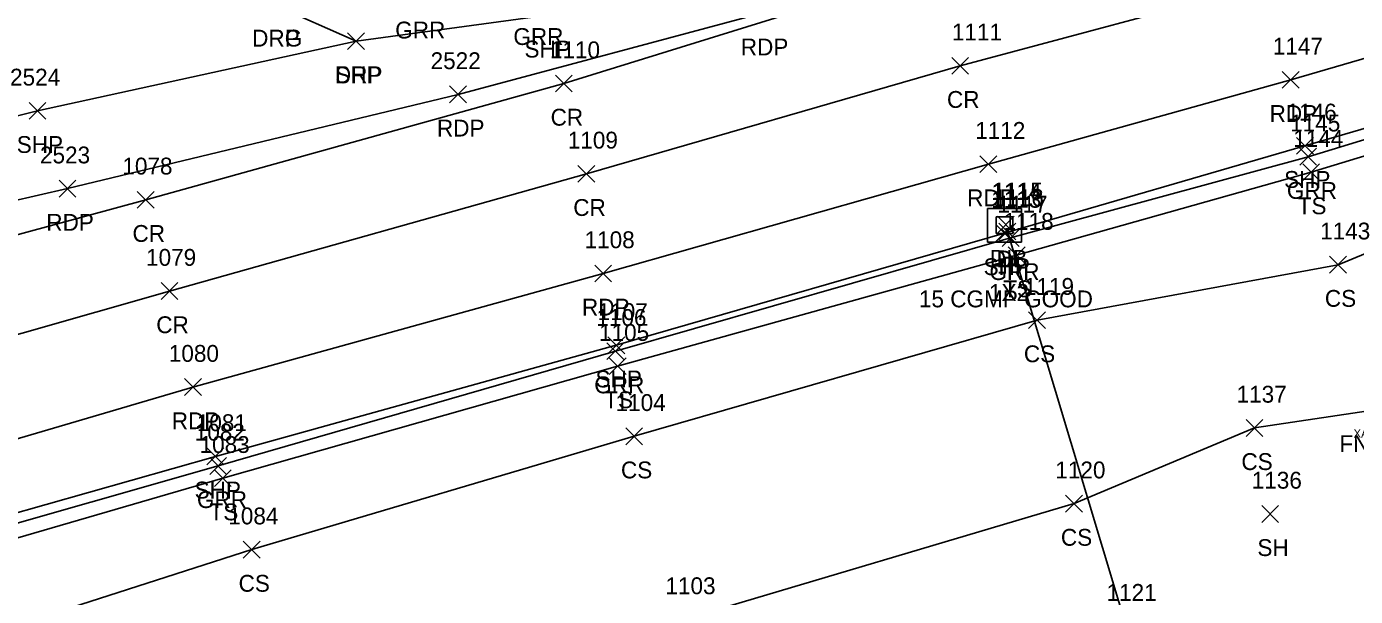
# Model space of a CAD drawing. Extents: x 49137 to 50946, y 9590 to 10709.
# Drawn here: x 49768.6 to 49926.3, y 9933.2 to 10000.8 of the extents above; entities that cross this region are included whole.
import ezdxf

# ---------------------------------------------------------------- set-up
doc = ezdxf.new("R2010")
doc.units = 0
for name, color, linetype in [('B_A', 7, 'Continuous'), ('D_A', 7, 'Continuous'), ('D_C', 7, 'Continuous'), ('D_I', 7, 'Continuous'), ('D_TIC', 7, 'Continuous'), ('DCP', 7, 'Continuous'), ('DS', 7, 'Continuous'), ('L_A', 7, 'Continuous'), ('L_I', 7, 'Continuous'), ('L_TIC', 7, 'Continuous'), ('LELB', 7, 'Continuous'), ('P_A', 7, 'Continuous'), ('P_I', 7, 'Continuous'), ('P_TIC', 7, 'Continuous'), ('PET', 7, 'Continuous'), ('PRC', 7, 'Continuous'), ('PSP', 7, 'Continuous'), ('R_A', 7, 'Continuous'), ('R_I', 7, 'Continuous'), ('R_TIC', 7, 'Continuous'), ('RDP', 7, 'Continuous'), ('RGR', 7, 'Continuous')]:
    doc.layers.add(name, color=color, linetype=linetype)

msp = doc.modelspace()

# ---------------------------------------------------------------- linework, layer by layer
at = {"layer": 'D_TIC'}
for points in [[(49883.82, 9976.31), (49885.82, 9978.31)], [(49885.82, 9976.31), (49883.82, 9978.31)], [(49884.01, 9975.49), (49886.01, 9977.49)], [(49886.01, 9975.49), (49884.01, 9977.49)]]:
    msp.add_lwpolyline(points, dxfattribs=at)
at = {"layer": 'DCP'}
msp.add_lwpolyline([(49885.01, 9976.49), (49907.56, 9901.46)], dxfattribs=at)
at = {"layer": 'DS'}
for p, q in [((49882.67, 9979.24), (49886.67, 9979.24)), ((49882.67, 9975.24), (49882.67, 9979.24)), ((49883.67, 9976.24), (49883.67, 9978.24)), ((49883.67, 9978.24), (49885.67, 9978.24)), ((49885.67, 9978.24), (49885.67, 9976.24)), ((49886.67, 9979.24), (49886.67, 9975.24)), ((49884.67, 9977.24), (49884.67, 9977.24)), ((49884.67, 9977.24), (49884.67, 9977.24)), ((49886.67, 9975.24), (49882.67, 9975.24)), ((49885.67, 9976.24), (49883.67, 9976.24))]:
    msp.add_line(p, q, dxfattribs=at)
at = {"layer": 'L_TIC'}
for points in [[(49920.06, 9982.54), (49922.06, 9984.54)], [(49922.06, 9982.54), (49920.06, 9984.54)], [(49885.11, 9972.69), (49887.11, 9974.69)], [(49887.11, 9972.69), (49885.11, 9974.69)], [(49923.25, 9971.55), (49925.25, 9973.55)], [(49925.25, 9971.55), (49923.25, 9973.55)], [(49887.53, 9964.97), (49889.53, 9966.97)], [(49889.53, 9964.97), (49887.53, 9966.97)], [(49837.75, 9959.51), (49839.75, 9961.51)], [(49839.75, 9959.51), (49837.75, 9961.51)], [(49839.71, 9951.18), (49841.71, 9953.18)], [(49841.71, 9951.18), (49839.71, 9953.18)], [(49913.34, 9952.17), (49915.34, 9954.17)], [(49915.34, 9952.17), (49913.34, 9954.17)], [(49790.91, 9946.2), (49792.91, 9948.2)], [(49792.91, 9946.2), (49790.91, 9948.2)], [(49891.92, 9943.18), (49893.92, 9945.18)], [(49893.92, 9943.18), (49891.92, 9945.18)], [(49915.19, 9941.96), (49917.19, 9943.96)], [(49917.19, 9941.96), (49915.19, 9943.96)], [(49794.33, 9937.72), (49796.33, 9939.72)], [(49796.33, 9937.72), (49794.33, 9939.72)]]:
    msp.add_lwpolyline(points, dxfattribs=at)
at = {"layer": 'LELB'}
for points in [[(49746.05, 9933.87), (49791.91, 9947.2), (49838.75, 9960.51), (49886.11, 9973.69), (49921.06, 9983.54), (49954.08, 9993.6), (49971.98, 9998.17), (49981.51, 9996.03), (50001.29, 9994.08), (50005.55, 10005.25), (50009.15, 10009.03), (50041.54, 10017.53), (50079.48, 10026.45), (50102.01, 10030.98), (50139.3, 10037.64), (50167.44, 10041.81), (50201.55, 10044.88)], [(49648.99, 9896.01), (49677.34, 9901.72), (49712.42, 9915.75), (49748.94, 9923.83), (49795.33, 9938.72), (49840.71, 9952.18), (49888.53, 9965.97), (49924.25, 9972.55), (49947.18, 9982.02)], [(49655.45, 9870.65), (49691.55, 9865.91), (49720.18, 9893.1), (49757.19, 9900.61), (49801.8, 9917.58), (49846.63, 9930.43), (49892.92, 9944.18), (49914.34, 9953.17), (49928.67, 9955.31)]]:
    msp.add_lwpolyline(points, dxfattribs=at)
at = {"layer": 'P_TIC'}
for points in [[(49806.71, 9998.09), (49808.71, 10000.09)], [(49808.71, 9998.09), (49806.71, 10000.09)], [(49878.41, 9995.17), (49880.41, 9997.17)], [(49880.41, 9995.17), (49878.41, 9997.17)], [(49917.64, 9993.5), (49919.64, 9995.5)], [(49919.64, 9993.5), (49917.64, 9995.5)], [(49818.82, 9991.77), (49820.82, 9993.77)], [(49820.82, 9991.77), (49818.82, 9993.77)], [(49831.37, 9993.06), (49833.37, 9995.06)], [(49833.37, 9993.06), (49831.37, 9995.06)], [(49768.91, 9989.82), (49770.91, 9991.82)], [(49770.91, 9989.82), (49768.91, 9991.82)], [(49919.32, 9985.67), (49921.32, 9987.67)], [(49921.32, 9985.67), (49919.32, 9987.67)], [(49834.05, 9982.34), (49836.05, 9984.34)], [(49836.05, 9982.34), (49834.05, 9984.34)], [(49881.75, 9983.49), (49883.75, 9985.49)], [(49883.75, 9983.49), (49881.75, 9985.49)], [(49772.46, 9980.58), (49774.46, 9982.58)], [(49774.46, 9980.58), (49772.46, 9982.58)], [(49781.75, 9979.26), (49783.75, 9981.26)], [(49783.75, 9979.26), (49781.75, 9981.26)], [(49883.65, 9975.31), (49885.65, 9977.31)], [(49885.65, 9975.31), (49883.65, 9977.31)], [(49836.04, 9970.51), (49838.04, 9972.51)], [(49838.04, 9970.51), (49836.04, 9972.51)], [(49784.57, 9968.42), (49786.57, 9970.42)], [(49786.57, 9968.42), (49784.57, 9970.42)], [(49837.6, 9961.98), (49839.6, 9963.98)], [(49839.6, 9961.98), (49837.6, 9963.98)], [(49787.35, 9957.02), (49789.35, 9959.02)], [(49789.35, 9957.02), (49787.35, 9959.02)], [(49790.02, 9948.79), (49792.02, 9950.79)], [(49792.02, 9948.79), (49790.02, 9950.79)]]:
    msp.add_lwpolyline(points, dxfattribs=at)
at = {"layer": 'PET'}
for points in [[(50495.53, 10081.77), (50449.66, 10088.73), (50401.7, 10093.22), (50356.33, 10094.93), (50326.68, 10095.17), (50279.7, 10093.24), (50237.68, 10090.37), (50191.91, 10084.51), (50151.19, 10077.89), (50119.21, 10071.6), (50086.72, 10064.4), (50053.97, 10056.46), (50026.35, 10049.68), (49981.17, 10037.41), (49930.4, 10023.11), (49891.41, 10012.39), (49855.88, 10002.4), (49819.82, 9992.77), (49773.46, 9981.58), (49739, 9973.69)], [(49743.42, 9944.81), (49788.35, 9958.02), (49837.04, 9971.51), (49882.75, 9984.49), (49918.64, 9994.5), (49951.14, 10003.99), (49990.91, 10015.05), (50038.8, 10027.76), (50078.38, 10036.75), (50102.79, 10041.88), (50136.94, 10048.02), (50166.81, 10052.31), (50203.48, 10056.47), (50244.74, 10059.59), (50274.3, 10060.67), (50312.69, 10061.26), (50351.88, 10059.79), (50388.42, 10057.55), (50415.03, 10055.45), (50437.05, 10053.05), (50478.42, 10048.42), (50499.95, 10044.65)]]:
    msp.add_lwpolyline(points, dxfattribs=at)
at = {"layer": 'PRC'}
for points in [[(49741.53, 9956.86), (49785.57, 9969.42), (49835.05, 9983.34), (49879.41, 9996.17), (49916.09, 10006.01), (49947.12, 10015.1), (49988.02, 10026.32), (50036.19, 10039.26), (50070.37, 10047.79), (50106.74, 10055.97), (50134.51, 10059.88), (50166.08, 10064.33), (50202.42, 10068.7), (50244.36, 10071.5), (50274.74, 10072.55), (50312.43, 10073.1), (50353.18, 10072.34), (50390.06, 10070.11), (50416.27, 10068.04), (50438.42, 10065.43), (50479.93, 10060.05), (50503.35, 10056.42)], [(49635.51, 9938.51), (49665.25, 9946.57), (49699.21, 9956.56), (49739.04, 9968.37), (49782.75, 9980.26), (49832.37, 9994.06), (49891.41, 10012.39)]]:
    msp.add_lwpolyline(points, dxfattribs=at)
at = {"layer": 'PSP'}
for points in [[(50496.83, 10085.32), (50450.63, 10092.03), (50402.39, 10096.53), (50359.36, 10098.82), (50327.14, 10099.23), (50280.12, 10097.78), (50237.97, 10094.88), (50191.64, 10089.51), (50150.54, 10083.69), (50117.84, 10077.88), (50085.62, 10071.48), (50052.95, 10063.95), (50024.27, 10056.62), (49980.23, 10044.39), (49928.03, 10029.66), (49890.75, 10019.13), (49853.57, 10008.09), (49830.16, 10002.15), (49807.71, 9999.09), (49769.91, 9990.82), (49738.16, 9982.81)], [(49745.77, 9936.94), (49791.02, 9949.79), (49838.6, 9962.98), (49884.65, 9976.31), (49920.32, 9986.67), (49952.97, 9996.21), (49993.49, 10007.72), (50041.55, 10020.44), (50079.02, 10029.05), (50103.84, 10034.11), (50138.34, 10040.53), (50167.13, 10044.8), (50204.38, 10048.62), (50245.47, 10052.53), (50273.99, 10052.71), (50313.27, 10053.81), (50350.86, 10052.67), (50388.17, 10050.83), (50414.17, 10048.89), (50435.24, 10046.38), (50477.89, 10041.39), (50498.49, 10037.53)]]:
    msp.add_lwpolyline(points, dxfattribs=at)
at = {"layer": 'R_TIC'}
for points in [[(49806.71, 9998.09), (49808.71, 10000.09)], [(49808.71, 9998.09), (49806.71, 10000.09)], [(49919.7, 9984.37), (49921.7, 9986.37)], [(49921.7, 9984.37), (49919.7, 9986.37)], [(49884.39, 9974.73), (49886.39, 9976.73)], [(49886.39, 9974.73), (49884.39, 9976.73)], [(49837.49, 9961.28), (49839.49, 9963.28)], [(49839.49, 9961.28), (49837.49, 9963.28)], [(49790.34, 9947.66), (49792.34, 9949.66)], [(49792.34, 9947.66), (49790.34, 9949.66)]]:
    msp.add_lwpolyline(points, dxfattribs=at)
at = {"layer": 'RDP'}
msp.add_lwpolyline([(49807.71, 9999.09), (49797.89, 10003.45), (49782.69, 10014.19), (49776.73, 10026.67), (49772.8, 10038.86), (49781.46, 10050.4), (49790.1, 10063.06), (49800.75, 10082.03)], dxfattribs=at)
at = {"layer": 'RGR'}
msp.add_lwpolyline([(49745.96, 9935.74), (49791.34, 9948.66), (49838.49, 9962.28), (49885.39, 9975.73), (49920.7, 9985.37), (49953.18, 9995.29), (49993.74, 10006.79), (50040.75, 10019.43), (50079.3, 10027.88), (50102.09, 10032.68), (50138.52, 10039.64), (50167.15, 10043.61), (50204.31, 10047.75), (50245.69, 10050.91), (50273.98, 10052), (50313.38, 10052.67), (50351, 10051.76), (50388.09, 10049.85), (50414.02, 10047.85), (50436.27, 10045.35), (50477.66, 10040.11), (50498.48, 10036.57)], dxfattribs=at)

# ---------------------------------------------------------------- texts
at = {"layer": 'B_A'}
msp.add_text('XAB', height=1, dxfattribs=at).set_placement((49926.09, 9952.01))
at = {"layer": 'D_A'}
for s, p in [('DIB', (49882.93, 9972.31)), ('DI', (49883.73, 9972.24)), ('P', (49884.38, 9971.49))]:
    msp.add_text(s, height=2, dxfattribs=at).set_placement(p)
at = {"layer": 'D_C'}
for s, p in [('1X2', (49882.82, 9968.24)), ('15 CGMP GOOD', (49874.51, 9967.49))]:
    msp.add_text(s, height=2, dxfattribs=at).set_placement(p)
at = {"layer": 'D_I'}
for s, p in [('1114', (49883.11, 9980.24)), ('1115', (49883.27, 9980.31)), ('1116', (49883.39, 9979.49))]:
    msp.add_text(s, height=2, dxfattribs=at).set_placement(p)
at = {"layer": 'L_A'}
for s, p in [('TS', (49919.46, 9978.54)), ('TS', (49884.52, 9968.69)), ('CS', (49922.69, 9967.55)), ('CS', (49886.97, 9960.97)), ('TS', (49837.16, 9955.51)), ('FNCHL', (49924.41, 9950.31)), ('CS', (49912.78, 9948.17)), ('CS', (49839.15, 9947.18)), ('TS', (49790.32, 9942.2)), ('CS', (49891.36, 9939.18)), ('SH', (49914.68, 9937.96)), ('CS', (49793.77, 9933.72))]:
    msp.add_text(s, height=2, dxfattribs=at).set_placement(p)
at = {"layer": 'L_I'}
for s, p in [('1144', (49918.93, 9986.54)), ('1118', (49884.55, 9976.69)), ('1143', (49922.13, 9975.55)), ('1119', (49886.97, 9968.97)), ('1105', (49836.55, 9963.51)), ('1137', (49912.21, 9956.17)), ('1104', (49838.51, 9955.18)), ('1083', (49789.14, 9950.2)), ('1120', (49890.7, 9947.18)), ('1136', (49914.01, 9945.96)), ('1084', (49792.55, 9941.72)), ('1103', (49844.43, 9933.43)), ('1121', (49896.78, 9932.64))]:
    msp.add_text(s, height=2, dxfattribs=at).set_placement(p)
at = {"layer": 'P_A'}
for s, p in [('SHP', (49827.7, 9997.15)), ('RDP', (49853.37, 9997.4)), ('SHP', (49805.25, 9994.09)), ('CR', (49877.84, 9991.17)), ('CR', (49830.8, 9989.06)), ('RDP', (49916.13, 9989.5)), ('RDP', (49817.31, 9987.77)), ('SHP', (49767.44, 9985.82)), ('SHP', (49917.85, 9981.67)), ('RDP', (49880.24, 9979.49)), ('CR', (49833.49, 9978.34)), ('RDP', (49770.95, 9976.58)), ('CR', (49781.18, 9975.26)), ('SHP', (49882.19, 9971.31)), ('RDP', (49834.52, 9966.51)), ('CR', (49784, 9964.42)), ('SHP', (49836.13, 9957.98)), ('RDP', (49785.84, 9953.02)), ('SHP', (49788.55, 9944.79))]:
    msp.add_text(s, height=2, dxfattribs=at).set_placement(p)
at = {"layer": 'P_I'}
for s, p in [('1111', (49878.42, 9999.17)), ('1110', (49830.72, 9997.06)), ('1147', (49916.51, 9997.5)), ('2522', (49816.56, 9995.77)), ('2524', (49766.65, 9993.82)), ('1146', (49918.14, 9989.67)), ('1112', (49881.19, 9987.49)), ('1109', (49832.84, 9986.34)), ('2523', (49770.2, 9984.58)), ('1078', (49779.98, 9983.26)), ('1113', (49883.09, 9979.31)), ('1108', (49834.83, 9974.51)), ('1079', (49782.79, 9972.42)), ('1107', (49836.39, 9965.98)), ('1080', (49785.49, 9961.02)), ('1081', (49788.81, 9952.79))]:
    msp.add_text(s, height=2, dxfattribs=at).set_placement(p)
at = {"layer": 'R_A'}
for s, p in [('DRG', (49795.38, 9998.45)), ('DRP', (49795.38, 9998.45)), ('GRR', (49812.36, 9999.41)), ('GRR', (49826.38, 9998.64)), ('DRP', (49805.2, 9994.09)), ('GRR', (49918.18, 9980.37)), ('GRR', (49882.88, 9970.73)), ('GRR', (49835.98, 9957.28)), ('GRR', (49788.83, 9943.66))]:
    msp.add_text(s, height=2, dxfattribs=at).set_placement(p)
at = {"layer": 'R_I'}
for s, p in [('1145', (49918.57, 9988.37)), ('1117', (49883.83, 9978.73)), ('1106', (49836.23, 9965.28)), ('1082', (49788.57, 9951.66))]:
    msp.add_text(s, height=2, dxfattribs=at).set_placement(p)

doc.saveas('drawing.dxf')
